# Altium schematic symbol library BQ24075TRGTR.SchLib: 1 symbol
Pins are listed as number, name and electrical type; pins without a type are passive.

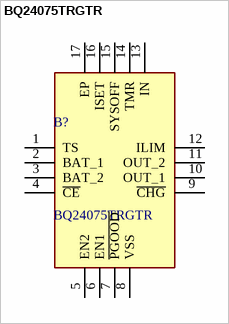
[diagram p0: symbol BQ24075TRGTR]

## BQ24075TRGTR
designator B?
1.5A USB-Friendly Li-Ion Battery Charger and Power-Path Management IC with 4.2 VBAT; Manufacturer_Name: Texas Instruments; Geometry.Height: 1mm
footprint QFN50P300X300X100-17N-D
pins: 1 TS, 2 BAT_1, 3 BAT_2, 4 ~{CE}, 5 EN2, 6 EN1, 7 ~{PGOOD}, 8 VSS, 9 ~{CHG}, 10 OUT_1, 11 OUT_2, 12 ILIM, 13 IN, 14 TMR, 15 SYSOFF, 16 ISET, 17 EP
